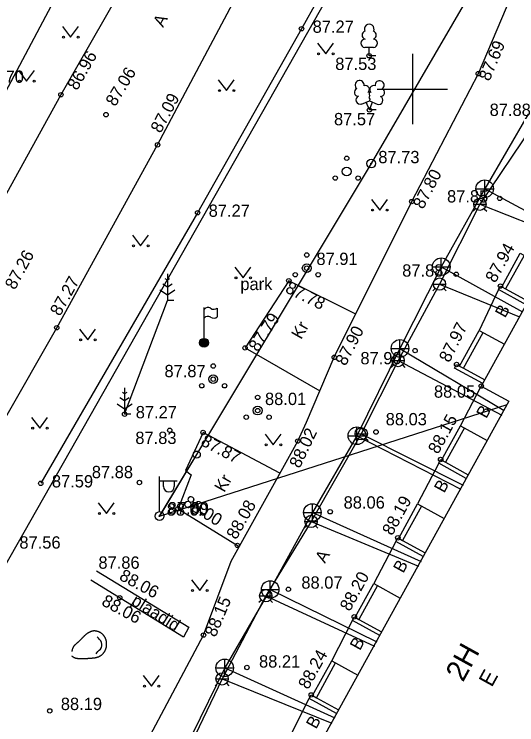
# Model space of a CAD drawing. Extents: x 648748 to 649126, y 6457789 to 6458252.
# Drawn here: x 648827.35 to 648855.94, y 6458013.84 to 6458054.26 of the extents above; entities that cross this region are included whole.
import ezdxf

# ---------------------------------------------------------------- set-up
doc = ezdxf.new("R2010")
doc.units = 0
for name, color, linetype in [('HALJASTUS', 7, 'Continuous'), ('HOONE', 7, 'Continuous'), ('HOONEDET', 7, 'Continuous'), ('KKAEV', 7, 'Continuous'), ('KORGUS-EH2000', 7, 'Continuous'), ('KTRASS', 7, 'Continuous'), ('MPOHULIIN', 7, 'Continuous'), ('PIIR', 7, 'Continuous'), ('POST', 7, 'Continuous'), ('PUU', 7, 'Continuous'), ('RAJATIS', 7, 'Continuous'), ('RELJEEF', 7, 'Continuous'), ('SITRASS', 7, 'Continuous'), ('TEE', 7, 'Continuous'), ('VKAEV', 7, 'Continuous'), ('VORK', 7, 'Continuous'), ('VTRASS', 7, 'Continuous')]:
    doc.layers.add(name, color=color, linetype=linetype)

msp = doc.modelspace()

# ---------------------------------------------------------------- linework, layer by layer
at = {"layer": 'HALJASTUS'}
for p, q in [((648830.093, 6458053.549), (648830.557, 6458052.943)), ((648830.557, 6458052.943), (648831.002, 6458053.549)), ((648844.606, 6458052.614), (648845.07, 6458052.007)), ((648845.07, 6458052.007), (648845.515, 6458052.614)), ((648827.593, 6458051.049), (648828.057, 6458050.443)), ((648828.057, 6458050.443), (648828.502, 6458051.049)), ((648838.961, 6458050.515), (648839.425, 6458049.909)), ((648839.425, 6458049.909), (648839.87, 6458050.515)), ((648847.677, 6458043.725), (648848.141, 6458043.119)), ((648848.141, 6458043.119), (648848.586, 6458043.725)), ((648834.081, 6458041.689), (648834.545, 6458041.083)), ((648834.545, 6458041.083), (648834.99, 6458041.689)), ((648839.906, 6458039.863), (648840.369, 6458039.256)), ((648840.369, 6458039.256), (648840.815, 6458039.863)), ((648831.071, 6458036.345), (648831.535, 6458035.739)), ((648831.535, 6458035.739), (648831.98, 6458036.345)), ((648828.342, 6458031.313), (648828.806, 6458030.706)), ((648828.806, 6458030.706), (648829.251, 6458031.313)), ((648841.628, 6458030.37), (648842.091, 6458029.763)), ((648842.091, 6458029.763), (648842.537, 6458030.37)), ((648832.135, 6458026.461), (648832.598, 6458025.854)), ((648832.598, 6458025.854), (648833.044, 6458026.461)), ((648837.44, 6458022.086), (648837.903, 6458021.48)), ((648837.903, 6458021.48), (648838.349, 6458022.086)), ((648834.694, 6458016.642), (648835.158, 6458016.035)), ((648835.158, 6458016.035), (648835.603, 6458016.642))]:
    msp.add_line(p, q, dxfattribs=at)
msp.add_lwpolyline([(648848.144, 6458061.397), (648843.695, 6458053.431), (648837.782, 6458042.965), (648828.866, 6458027.575)], dxfattribs=at)
for centre in [(648830.156, 6458052.943), (648830.985, 6458052.943), (648844.669, 6458052.007), (648845.498, 6458052.007), (648827.656, 6458050.443), (648828.485, 6458050.443), (648839.024, 6458049.909), (648839.853, 6458049.909), (648847.74, 6458043.119), (648848.569, 6458043.119), (648834.144, 6458041.083), (648834.973, 6458041.083), (648839.968, 6458039.256), (648840.797, 6458039.256), (648831.134, 6458035.739), (648831.963, 6458035.739), (648828.405, 6458030.706), (648829.234, 6458030.706), (648841.69, 6458029.763), (648842.519, 6458029.763), (648832.197, 6458025.854), (648833.026, 6458025.854), (648837.502, 6458021.48), (648838.331, 6458021.48), (648834.757, 6458016.035), (648835.586, 6458016.035)]:
    msp.add_circle(centre, 0.055, dxfattribs=at)
at = {"layer": 'HOONE'}
for points in [[(648871.67, 6458059.037), (648869.02, 6458060.498), (648853.919, 6458033.105), (648855.485, 6458032.242), (648840.687, 6458005.398), (648842.333, 6458004.491), (648827.567, 6457977.705), (648832.374, 6457975.097)], [(648856.466, 6458037.725), (648854.897, 6458038.59), (648855.01, 6458038.795), (648855.085, 6458038.754), (648856.136, 6458040.661), (648857.631, 6458039.837)], [(648853.999, 6458033.25), (648852.403, 6458034.129), (648852.516, 6458034.334), (648852.683, 6458034.242), (648853.803, 6458036.273), (648855.232, 6458035.486)], [(648853.067, 6458027.856), (648851.495, 6458028.723), (648851.608, 6458028.928), (648851.663, 6458028.897), (648852.74, 6458030.85), (648854.257, 6458030.013)], [(648850.618, 6458023.412), (648849.059, 6458024.272), (648849.172, 6458024.476), (648849.222, 6458024.449), (648850.298, 6458026.402), (648851.807, 6458025.57)], [(648848.14, 6458018.919), (648846.585, 6458019.776), (648846.698, 6458019.981), (648846.738, 6458019.959), (648847.799, 6458021.883), (648849.314, 6458021.048)], [(648845.692, 6458014.478), (648844.133, 6458015.338), (648844.246, 6458015.543), (648844.322, 6458015.5), (648845.412, 6458017.477), (648846.895, 6458016.659)]]:
    msp.add_lwpolyline(points, dxfattribs=at)
at = {"layer": 'HOONEDET'}
for p, q in [((648856.355, 6458040.541), (648855.304, 6458038.633)), ((648852.902, 6458034.121), (648854.022, 6458036.153)), ((648852.959, 6458030.729), (648851.882, 6458028.776)), ((648850.517, 6458026.281), (648849.441, 6458024.328)), ((648848.018, 6458021.762), (648846.957, 6458019.838)), ((648844.541, 6458015.38), (648845.631, 6458017.356))]:
    msp.add_line(p, q, dxfattribs=at)
for points in [[(648855.085, 6458038.754), (648855.304, 6458038.633), (648856.579, 6458037.93)], [(648852.683, 6458034.242), (648852.902, 6458034.121), (648854.112, 6458033.454)], [(648851.663, 6458028.897), (648851.882, 6458028.776), (648853.18, 6458028.061)], [(648849.222, 6458024.449), (648849.441, 6458024.328), (648850.731, 6458023.617)], [(648846.738, 6458019.959), (648846.957, 6458019.838), (648848.253, 6458019.123)], [(648844.322, 6458015.5), (648844.541, 6458015.38), (648845.805, 6458014.683)]]:
    msp.add_lwpolyline(points, dxfattribs=at)
at = {"layer": 'KKAEV'}
for p, q in [((648854.114, 6458043.829), (648854.114, 6458044.829)), ((648853.614, 6458044.329), (648854.614, 6458044.329)), ((648851.641, 6458039.395), (648851.641, 6458040.395)), ((648851.141, 6458039.895), (648852.141, 6458039.895)), ((648849.293, 6458034.748), (648849.293, 6458035.748)), ((648848.793, 6458035.248), (648849.793, 6458035.248)), ((648846.845, 6458029.781), (648846.845, 6458030.781)), ((648846.345, 6458030.281), (648847.345, 6458030.281)), ((648844.311, 6458025.414), (648844.311, 6458026.414)), ((648843.811, 6458025.914), (648844.811, 6458025.914)), ((648841.912, 6458021.037), (648841.912, 6458022.037)), ((648841.412, 6458021.537), (648842.412, 6458021.537)), ((648839.326, 6458016.576), (648839.326, 6458017.576)), ((648838.826, 6458017.076), (648839.826, 6458017.076))]:
    msp.add_line(p, q, dxfattribs=at)
for centre in [(648854.114, 6458044.329), (648851.641, 6458039.895), (648849.293, 6458035.248), (648846.845, 6458030.281), (648844.311, 6458025.914), (648841.912, 6458021.537), (648839.326, 6458017.076)]:
    msp.add_circle(centre, 0.5, dxfattribs=at)
at = {"layer": 'KORGUS-EH2000'}
for centre in [(648843.695, 6458053.431), (648847.543, 6458051.891), (648853.751, 6458050.875), (648830.008, 6458049.677), (648832.574, 6458048.543), (648847.554, 6458048.813), (648835.506, 6458046.826), (648849.963, 6458043.601), (648854.97, 6458043.781), (648837.782, 6458042.965), (648843.991, 6458039.812), (648852.493, 6458039.463), (648842.972, 6458039.095), (648855.01, 6458038.795), (648829.771, 6458036.425), (648840.482, 6458035.275), (648850.156, 6458035.126), (648845.559, 6458034.741), (648852.516, 6458034.334), (648838.672, 6458033.497), (648853.919, 6458033.105), (648833.633, 6458031.507), (648841.2, 6458031.713), (648836.2, 6458030.591), (648838.095, 6458030.467), (648847.93, 6458030.493), (648843.481, 6458029.976), (648851.608, 6458028.928), (648828.866, 6458027.575), (648834.474, 6458027.62), (648836.67, 6458026.131), (648845.324, 6458025.956), (648849.172, 6458024.476), (648840.05, 6458024.044), (648842.948, 6458021.549), (648833.358, 6458021.065), (648846.698, 6458019.981), (648838.119, 6458018.946), (648840.592, 6458017.101), (648844.246, 6458015.543), (648829.374, 6458014.632)]:
    msp.add_circle(centre, 0.125, dxfattribs=at)
at = {"layer": 'KTRASS'}
for p, q in [((648856.587, 6458048.575), (648854.114, 6458044.329)), ((648854.114, 6458044.329), (648851.641, 6458039.895)), ((648854.114, 6458044.329), (648858.745, 6458041.841)), ((648851.641, 6458039.895), (648849.293, 6458035.248)), ((648851.641, 6458039.895), (648856.255, 6458037.322)), ((648849.293, 6458035.248), (648846.845, 6458030.281)), ((648849.293, 6458035.248), (648855.221, 6458031.712)), ((648846.845, 6458030.281), (648844.311, 6458025.914)), ((648846.845, 6458030.281), (648852.758, 6458027.242)), ((648844.311, 6458025.914), (648841.912, 6458021.537)), ((648844.311, 6458025.914), (648850.491, 6458023.128)), ((648841.912, 6458021.537), (648839.326, 6458017.076)), ((648841.912, 6458021.537), (648847.977, 6458018.565)), ((648839.326, 6458017.076), (648837.456, 6458013.243)), ((648839.326, 6458017.076), (648845.593, 6458014.238))]:
    msp.add_line(p, q, dxfattribs=at)
at = {"layer": 'MPOHULIIN'}
for p, q in [((648863.647, 6458073.263), (648847.655, 6458045.759)), ((648847.655, 6458045.759), (648835.622, 6458025.713)), ((648835.622, 6458025.713), (648855.384, 6458032.059))]:
    msp.add_line(p, q, dxfattribs=at)
at = {"layer": 'PIIR'}
msp.add_line((648796.52, 6457969.47), (648863.67, 6458087.81), dxfattribs=at)
at = {"layer": 'POST'}
for p, q in [((648835.622, 6458025.713), (648837.738, 6458029.212)), ((648835.622, 6458025.963), (648835.622, 6458027.963)), ((648835.622, 6458027.713), (648836.622, 6458027.713)), ((648835.849, 6458027.392), (648835.849, 6458027.713)), ((648836.462, 6458027.392), (648836.462, 6458027.713))]:
    msp.add_line(p, q, dxfattribs=at)
for centre, radius in [((648847.655, 6458045.759), 0.25), ((648847.655, 6458045.759), 0.0234), ((648837.738, 6458029.212), 0.2), ((648835.622, 6458025.713), 0.25), ((648835.622, 6458025.713), 0.0234)]:
    msp.add_circle(centre, radius, dxfattribs=at)
msp.add_arc((648836.155, 6458027.392), 0.306, 180, 0, dxfattribs=at)
at = {"layer": 'PUU'}
for p, q in [((648847.783, 6458052.366), (648847.303, 6458052.366)), ((648847.543, 6458051.891), (648847.543, 6458052.366)), ((648847.923, 6458051.891), (648847.543, 6458051.891)), ((648847.113, 6458049.148), (648847.559, 6458049.323)), ((648847.554, 6458048.813), (648847.378, 6458049.253)), ((648847.554, 6458048.813), (648847.733, 6458049.253)), ((648847.559, 6458049.323), (648847.998, 6458049.143)), ((648847.934, 6458048.813), (648847.554, 6458048.813)), ((648836.064, 6458039.481), (648836.064, 6458037.981)), ((648836.064, 6458038.731), (648835.798, 6458038.909)), ((648836.064, 6458039.131), (648835.94, 6458039.214)), ((648836.189, 6458039.214), (648836.064, 6458039.131)), ((648836.331, 6458038.909), (648836.064, 6458038.731)), ((648835.64, 6458038.571), (648836.064, 6458038.288)), ((648836.064, 6458038.288), (648836.489, 6458038.571)), ((648833.633, 6458031.507), (648836.071, 6458037.981)), ((648836.424, 6458037.981), (648836.064, 6458037.981)), ((648833.633, 6458033.007), (648833.633, 6458031.507)), ((648833.633, 6458032.257), (648833.367, 6458032.434)), ((648833.633, 6458032.657), (648833.509, 6458032.74)), ((648833.758, 6458032.74), (648833.633, 6458032.657)), ((648833.9, 6458032.434), (648833.633, 6458032.257)), ((648833.209, 6458032.096), (648833.633, 6458031.813)), ((648833.633, 6458031.813), (648834.058, 6458032.096)), ((648833.993, 6458031.507), (648833.633, 6458031.507))]:
    msp.add_line(p, q, dxfattribs=at)
msp.add_lwpolyline([(648847.559, 6458049.818), (648847.539, 6458049.743), (648847.539, 6458049.723), (648847.549, 6458049.693), (648847.569, 6458049.658), (648847.574, 6458049.638), (648847.559, 6458049.603), (648847.534, 6458049.553), (648847.529, 6458049.528), (648847.534, 6458049.513), (648847.544, 6458049.483), (648847.579, 6458049.423), (648847.584, 6458049.403), (648847.579, 6458049.383), (648847.564, 6458049.348), (648847.559, 6458049.323)], dxfattribs=at)
for centre, radius in [((648846.265, 6458046.061), 0.125), ((648846.265, 6458045.311), 0.25), ((648845.615, 6458044.936), 0.125), ((648846.915, 6458044.936), 0.125), ((648843.991, 6458040.562), 0.125), ((648843.991, 6458039.812), 0.25), ((648843.341, 6458039.437), 0.125), ((648844.641, 6458039.437), 0.125), ((648838.672, 6458034.247), 0.125), ((648838.672, 6458033.497), 0.25), ((648838.022, 6458033.122), 0.125), ((648839.322, 6458033.122), 0.125), ((648841.2, 6458032.463), 0.125), ((648841.2, 6458031.713), 0.25), ((648840.55, 6458031.338), 0.125), ((648841.85, 6458031.338), 0.125)]:
    msp.add_circle(centre, radius, dxfattribs=at)
for centre, radius, start, end in [((648847.543, 6458053.411), 0.277, 332.58, 207.42), ((648847.373, 6458053.064), 0.233, 109.022, 253.142), ((648847.713, 6458053.064), 0.233, 286.851, 70.986), ((648847.305, 6458052.604), 0.238, 90.002, 269.395), ((648847.78, 6458052.604), 0.238, 270.605, 89.998), ((648846.997, 6458050.227), 0.256, 111.503, 232.517), ((648846.997, 6458050.227), 0.256, 350.486, 111.5), ((648847.331, 6458049.977), 0.224, 308.504, 111.572), ((648847.794, 6458049.972), 0.225, 67.702, 230.513), ((648848.133, 6458050.219), 0.256, 67.617, 188.631), ((648848.133, 6458050.219), 0.256, 306.6, 67.614), ((648846.922, 6458049.816), 0.224, 111.43, 274.499), ((648847.557, 6458049.581), 0.237, 66.766, 111.501), ((648848.2, 6458049.806), 0.224, 264.618, 67.687), ((648847.027, 6458049.372), 0.237, 111.501, 291.5), ((648848.089, 6458049.364), 0.238, 247.617, 67.616)]:
    msp.add_arc(centre, radius, start, end, dxfattribs=at)
at = {"layer": 'RAJATIS'}
for p, q in [((648838.151, 6458035.821), (648838.151, 6458037.571)), ((648838.904, 6458037.54), (648838.904, 6458037.04))]:
    msp.add_line(p, q, dxfattribs=at)
for radius in [0.25, 0.225, 0.2, 0.175, 0.15, 0.125, 0.1, 0.075, 0.05, 0.025]:
    msp.add_circle((648838.151, 6458035.571), radius, dxfattribs=at)
for centre, radius, start, end in [((648838.375, 6458037.286), 0.288, 57.9503, 140.7766), ((648838.709, 6458037.818), 0.341, 237.8349, 305.0521), ((648838.375, 6458036.786), 0.288, 57.9503, 140.7766), ((648838.709, 6458037.318), 0.341, 237.8349, 305.0521)]:
    msp.add_arc(centre, radius, start, end, dxfattribs=at)
at = {"layer": 'RELJEEF'}
msp.add_lwpolyline([(648832.008, 6458017.885), (648832.051, 6458017.93), (648832.119, 6458018.003), (648832.187, 6458018.076), (648832.255, 6458018.15), (648832.311, 6458018.232), (648832.336, 6458018.328), (648832.337, 6458018.428), (648832.316, 6458018.526), (648832.273, 6458018.616), (648832.21, 6458018.694), (648832.145, 6458018.769), (648832.079, 6458018.844)], dxfattribs=at)
msp.add_open_spline([(648830.623, 6458017.765), (648830.623, 6458017.765), (648830.628, 6458017.756), (648830.822, 6458017.627), (648831.072, 6458017.615), (648831.322, 6458017.614), (648831.572, 6458017.621), (648831.821, 6458017.639), (648832.068, 6458017.674), (648832.294, 6458017.776), (648832.47, 6458017.953), (648832.583, 6458018.174), (648832.618, 6458018.421), (648832.589, 6458018.669), (648832.481, 6458018.893), (648832.301, 6458019.064), (648832.075, 6458019.168), (648831.828, 6458019.188), (648831.597, 6458019.094), (648831.394, 6458018.95), (648831.22, 6458018.771), (648831.047, 6458018.59), (648830.858, 6458018.427), (648830.676, 6458018.258), (648830.632, 6458018.015)], degree=2, dxfattribs=at)
at = {"layer": 'SITRASS'}
msp.add_lwpolyline([(648840.698, 6458076.036), (648840.206, 6458074.518), (648835.992, 6458066.48), (648829.455, 6458054.737), (648823.386, 6458043.337), (648816.202, 6458031.074), (648810.097, 6458020.648), (648803.233, 6458008.294), (648797.369, 6457997.813), (648791.835, 6457987.5), (648788.847, 6457982.267), (648783.409, 6457971.182), (648777.403, 6457959.148), (648772.285, 6457949.688)], dxfattribs=at)
at = {"layer": 'TEE'}
for p, q in [((648854.897, 6458038.59), (648853.803, 6458036.273)), ((648852.74, 6458030.85), (648853.919, 6458033.105)), ((648851.495, 6458028.723), (648850.298, 6458026.402)), ((648849.059, 6458024.272), (648847.799, 6458021.883)), ((648845.412, 6458017.477), (648846.585, 6458019.776)), ((648842.939, 6458012.973), (648844.133, 6458015.338))]:
    msp.add_line(p, q, dxfattribs=at)
for points in [[(648809.885, 6457960.062), (648810.233, 6457960.629), (648815.43, 6457971.592), (648817.584, 6457976.36), (648820.136, 6457981.696), (648823.114, 6457989.321), (648828.108, 6457999.323), (648833.019, 6458009.341), (648838.119, 6458018.946), (648839.695, 6458023.154), (648843.481, 6458029.976), (648843.97, 6458031.062), (648845.559, 6458034.741), (648849.963, 6458043.601), (648853.751, 6458050.875), (648857.741, 6458060.282), (648859.244, 6458064.865), (648859.613, 6458067.904), (648859.358, 6458070.552), (648857.99, 6458075.311), (648855.198, 6458076.755), (648851.865, 6458076.18), (648849.159, 6458071.672)], [(648844.3, 6458074.59), (648841.568, 6458069.96), (648835.932, 6458060.036), (648830.008, 6458049.677), (648824.317, 6458039.384), (648818.356, 6458028.958), (648812.613, 6458018.629), (648806.656, 6458008.281), (648800.566, 6457997.472), (648794.382, 6457986.281), (648790.808, 6457979.567), (648784.572, 6457968.758), (648779.694, 6457960.62), (648774.527, 6457951.036)], [(648795.708, 6457976.678), (648799.747, 6457983.584), (648805.652, 6457994.165), (648811.974, 6458005.315), (648817.667, 6458015.456), (648823.8, 6458025.997), (648829.771, 6458036.425), (648835.506, 6458046.826), (648841.055, 6458057.292), (648846.734, 6458067.377), (648849.159, 6458071.672)], [(648846.777, 6458037.193), (648842.972, 6458039.095), (648840.482, 6458035.275), (648844.734, 6458032.831)], [(648842.47, 6458028.154), (648838.095, 6458030.467), (648837.093, 6458028.309), (648837.424, 6458028.049), (648836.67, 6458026.131), (648840.154, 6458023.98)], [(648832.036, 6458022.593), (648837.28, 6458019.391), (648836.992, 6458018.828), (648831.717, 6458022.075)]]:
    msp.add_lwpolyline(points, dxfattribs=at)
at = {"layer": 'VKAEV'}
for p, q in [((648853.49, 6458043.444), (648854.19, 6458043.444)), ((648853.593, 6458043.196), (648853.453, 6458043.057)), ((648854.088, 6458043.196), (648854.227, 6458043.057)), ((648851.192, 6458038.91), (648851.892, 6458038.91)), ((648851.295, 6458038.663), (648851.155, 6458038.523)), ((648851.79, 6458038.663), (648851.929, 6458038.523)), ((648848.837, 6458034.556), (648849.537, 6458034.556)), ((648848.94, 6458034.309), (648848.8, 6458034.169)), ((648849.435, 6458034.309), (648849.574, 6458034.169)), ((648846.741, 6458030.397), (648847.441, 6458030.397)), ((648846.844, 6458030.15), (648846.704, 6458030.01)), ((648847.339, 6458030.15), (648847.478, 6458030.01)), ((648843.99, 6458025.161), (648843.85, 6458025.021)), ((648843.887, 6458025.408), (648844.587, 6458025.408)), ((648844.485, 6458025.161), (648844.624, 6458025.021)), ((648841.308, 6458021.177), (648842.008, 6458021.177)), ((648841.411, 6458020.93), (648841.271, 6458020.79)), ((648841.906, 6458020.93), (648842.045, 6458020.79)), ((648838.828, 6458016.45), (648839.528, 6458016.45)), ((648838.931, 6458016.203), (648838.791, 6458016.063)), ((648839.426, 6458016.203), (648839.565, 6458016.063))]:
    msp.add_line(p, q, dxfattribs=at)
for centre in [(648853.84, 6458043.444), (648851.542, 6458038.91), (648849.187, 6458034.556), (648847.091, 6458030.397), (648844.237, 6458025.408), (648841.658, 6458021.177), (648839.178, 6458016.45)]:
    msp.add_circle(centre, 0.35, dxfattribs=at)
at = {"layer": 'VORK'}
for p, q in [((648850, 6458052), (648850, 6458048)), ((648848, 6458050), (648852, 6458050))]:
    msp.add_line(p, q, dxfattribs=at)
at = {"layer": 'VTRASS'}
for p, q in [((648853.84, 6458043.444), (648858.594, 6458041.566)), ((648851.542, 6458038.91), (648856.099, 6458037.039)), ((648849.187, 6458034.556), (648855.079, 6458031.454)), ((648847.091, 6458030.397), (648852.884, 6458027.471)), ((648844.237, 6458025.408), (648850.345, 6458022.862)), ((648841.658, 6458021.177), (648847.837, 6458018.31)), ((648839.178, 6458016.45), (648845.428, 6458013.939))]:
    msp.add_line(p, q, dxfattribs=at)
msp.add_lwpolyline([(648864.219, 6458061.359), (648861.546, 6458056.334), (648859.119, 6458052.469), (648856.855, 6458047.93), (648853.84, 6458043.444), (648851.542, 6458038.91), (648849.187, 6458034.556), (648847.091, 6458030.397), (648844.237, 6458025.408), (648841.658, 6458021.177), (648839.178, 6458016.45), (648837.21, 6458012.35), (648834.536, 6458007.426), (648832.327, 6458003.249), (648829.651, 6457998.416), (648827.169, 6457994.074), (648824.746, 6457989.896), (648822.496, 6457985.078), (648821.983, 6457983.396), (648822.36, 6457981.31), (648825.099, 6457977.566), (648828.129, 6457973.95), (648829.36, 6457973.21)], dxfattribs=at)

# ---------------------------------------------------------------- texts
at = {"layer": 'HALJASTUS'}
msp.add_text('park', height=0.7, dxfattribs=at).set_placement((648840.216, 6458038.564))
at = {"layer": 'HOONE'}
for s, height, p in [('2H', 1.2, (648852.875, 6458016.227)), ('E', 0.9, (648854.516, 6458015.94))]:
    msp.add_text(s, height=height, rotation=61.1339, dxfattribs=at).set_placement(p)
at = {"layer": 'KORGUS-EH2000'}
for s, p in [(' 87.27', (648844.067, 6458053.198)), ('87.53', (648845.612, 6458051.084)), (' 86.70', (648825.303, 6458050.353)), ('87.88', (648854.394, 6458048.47)), ('87.57', (648845.542, 6458047.94)), ('87.73', (648848.062, 6458045.782)), ('87.85', (648851.971, 6458043.548)), (' 87.27', (648838.154, 6458042.732)), ('87.91', (648844.543, 6458039.993)), ('87.88', (648849.42, 6458039.33)), ('87.90', (648847.044, 6458034.344)), ('87.87', (648835.9, 6458033.611)), ('88.05', (648851.227, 6458032.445)), ('88.01', (648841.618, 6458032.028)), (' 87.27', (648834.006, 6458031.273)), ('88.03', (648848.482, 6458030.874)), ('87.83', (648834.243, 6458029.811)), ('87.88', (648831.769, 6458027.867)), (' 87.59', (648829.238, 6458027.342)), ('88.06', (648846.089, 6458026.137)), ('88.00', (648836.029, 6458025.736)), ('87.89', (648836.084, 6458025.811)), (' 87.56', (648827.389, 6458023.861)), ('87.86', (648832.144, 6458022.718)), ('88.07', (648843.686, 6458021.583)), ('88.21', (648841.278, 6458017.095)), ('88.19', (648830.006, 6458014.679))]:
    msp.add_text(s, height=0.7, dxfattribs=at).set_placement(p)
for s, rotation, p in [('87.69', 67.0151, (648854.379, 6458050.406)), (' 86.96', 60.2342, (648830.8, 6458049.653)), (' 87.06', 58.8637, (648832.966, 6458048.741)), (' 87.09', 62.0669, (648835.561, 6458047.218)), ('87.80', 62.4894, (648850.609, 6458043.124)), ('87.94', 61.1339, (648854.715, 6458038.93)), (' 87.26', 61.4399, (648827.269, 6458038.308)), (' 87.27', 61.1273, (648829.835, 6458036.814)), ('87.78', 333.4471, (648842.718, 6458038.469)), ('87.79', 56.9083, (648841.212, 6458035.009)), ('87.90', 62.846, (648846.197, 6458034.209)), ('87.97', 63.342, (648852.099, 6458034.401)), ('88.15', 61.1339, (648851.459, 6458029.191)), ('88.02', 64.2847, (648843.587, 6458028.387)), ('87.87', 332.1327, (648837.912, 6458029.772)), ('88.00', 328.3073, (648836.91, 6458026.346)), ('88.19', 61.1339, (648848.849, 6458024.56)), ('88.08', 60.4287, (648839.981, 6458024.332)), ('88.06', 331.6421, (648833.275, 6458022.121)), ('88.20', 61.1339, (648846.441, 6458020.249)), ('88.06', 331.6589, (648832.269, 6458020.676)), ('88.15', 67.1355, (648838.803, 6458018.783)), ('88.24', 61.1339, (648844.07, 6458015.808))]:
    msp.add_text(s, height=0.7, rotation=rotation, dxfattribs=at).set_placement(p)
at = {"layer": 'TEE'}
for s, rotation, p in [('A', 62.2738, (648835.824, 6458053.47)), ('B', 61.1339, (648855.273, 6458036.943)), ('Kr', 60.3409, (648843.676, 6458035.717)), ('B', 61.1339, (648854.203, 6458031.219)), ('Kr', 60.3409, (648839.302, 6458027.015)), ('B', 61.1339, (648851.806, 6458026.984)), ('A', 60.3409, (648845.029, 6458022.989)), ('B', 61.1339, (648849.479, 6458022.424)), ('plaadid', 328.0111, (648833.951, 6458020.72)), ('B', 61.1339, (648847.013, 6458018.026)), ('B', 61.1339, (648844.523, 6458013.559))]:
    msp.add_text(s, height=0.7, rotation=rotation, dxfattribs=at).set_placement(p)

doc.saveas('drawing.dxf')
